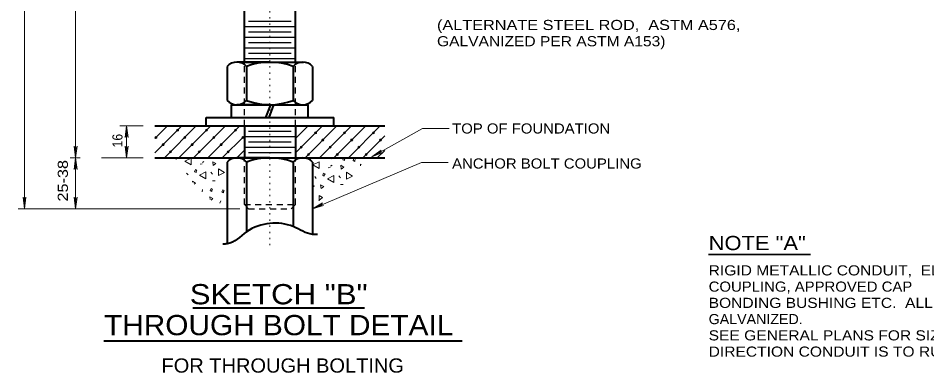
# Model space of a CAD drawing. Extents: x 312583 to 312854, y 144419 to 144597.
# Drawn here: x 312716.3 to 312784.5, y 144522.8 to 144549.4 of the extents above; entities that cross this region are included whole.
import ezdxf
from ezdxf.enums import TextEntityAlignment as Align

# ---------------------------------------------------------------- set-up
doc = ezdxf.new("R2010")
doc.units = 0
doc.header["$LTSCALE"] = 0.3
doc.header["$PDMODE"] = 32
doc.header["$PDSIZE"] = 0.15
doc.linetypes.add('DOTTED', pattern=[1.5, 0.3, -1.2])
doc.linetypes.add('SHORT_DASHED', pattern=[2.7, 1.5, -1.2])
doc.layers.add('1', color=7, linetype='Continuous', lineweight=25)
doc.layers.add('2', color=7, linetype='Continuous', lineweight=13)

msp = doc.modelspace()

# ---------------------------------------------------------------- linework, layer by layer
at = {"layer": '1', "linetype": 'DOTTED', "lineweight": 13}
msp.add_line((312735.2298, 144532.3427), (312735.2298, 144581.2407), dxfattribs=at)
at = {"layer": '1', "lineweight": 40}
for p, q in [((312733.3132, 144546.0967), (312733.3132, 144562.3884)), ((312737.1465, 144546.0967), (312737.1465, 144562.3884)), ((312735.2298, 144546.0967), (312732.7535, 144546.0967)), ((312733.3132, 144546.0967), (312737.7522, 144546.0967)), ((312735.2298, 144546.0967), (312737.6985, 144546.0967)), ((312732.0328, 144545.7747), (312732.0328, 144543.2217)), ((312733.4742, 144545.7747), (312733.4742, 144543.2217)), ((312733.4742, 144545.7747), (312733.4742, 144543.2217)), ((312736.9855, 144545.7747), (312736.9855, 144543.2217)), ((312738.4192, 144545.7747), (312738.4192, 144543.2217)), ((312732.3548, 144542.8997), (312738.0972, 144542.8997)), ((312732.3548, 144541.9414), (312732.3548, 144542.8997)), ((312735.2298, 144542.8997), (312732.7535, 144542.8997)), ((312734.9385, 144541.9414), (312735.2912, 144542.8997)), ((312735.1762, 144541.9414), (312735.5288, 144542.8997)), ((312735.2298, 144542.8997), (312737.6985, 144542.8997)), ((312738.0972, 144541.9414), (312738.0972, 144542.8997)), ((312730.4382, 144541.9414), (312740.0215, 144541.9414)), ((312730.4382, 144541.305), (312730.4382, 144541.9414)), ((312740.0215, 144541.305), (312740.0215, 144541.9414)), ((312726.6048, 144541.305), (312743.8472, 144541.305)), ((312733.3132, 144541.305), (312733.3132, 144538.913)), ((312737.1465, 144541.305), (312737.1465, 144538.913)), ((312726.6048, 144538.913), (312743.8472, 144538.913)), ((312732.0328, 144538.591), (312732.0328, 144532.45)), ((312735.2298, 144538.913), (312732.7535, 144538.913)), ((312733.3132, 144538.913), (312737.7522, 144538.913)), ((312733.4742, 144538.591), (312733.4742, 144533.347)), ((312733.4742, 144538.591), (312733.4742, 144536.038)), ((312735.2298, 144538.913), (312737.6985, 144538.913)), ((312736.9855, 144538.591), (312736.9855, 144533.7457)), ((312738.4192, 144538.591), (312738.4192, 144533.163))]:
    msp.add_line(p, q, dxfattribs=at)
at = {"layer": '1'}
for p, q in [((312733.3132, 144548.7724), (312737.1465, 144548.7724)), ((312733.6275, 144549.171), (312736.8245, 144549.171)), ((312733.6275, 144548.366), (312736.8245, 144548.366)), ((312733.3132, 144547.9674), (312737.1465, 144547.9674)), ((312733.6275, 144547.5687), (312736.8245, 144547.5687)), ((312733.3132, 144547.17), (312737.1465, 144547.17)), ((312733.6275, 144546.7637), (312736.8245, 144546.7637)), ((312733.3132, 144546.365), (312737.1465, 144546.365)), ((312733.6275, 144540.9064), (312736.8245, 144540.9064)), ((312733.3132, 144540.5077), (312737.1465, 144540.5077)), ((312733.6275, 144540.109), (312736.8245, 144540.109)), ((312733.3132, 144539.7104), (312737.1465, 144539.7104)), ((312733.6275, 144539.3117), (312736.8245, 144539.3117))]:
    msp.add_line(p, q, dxfattribs=at)
at = {"layer": '1', "linetype": 'SHORT_DASHED'}
for p, q in [((312733.3132, 144541.305), (312733.3132, 144546.0967)), ((312737.1465, 144541.305), (312737.1465, 144546.0967)), ((312733.3132, 144535.394), (312733.3132, 144538.913)), ((312737.1465, 144535.394), (312737.1465, 144538.913)), ((312733.3132, 144535.394), (312733.6275, 144535.0797)), ((312733.3132, 144535.394), (312737.1465, 144535.394)), ((312733.6275, 144535.0797), (312736.8245, 144535.0797)), ((312736.8245, 144535.0797), (312737.1465, 144535.394))]:
    msp.add_line(p, q, dxfattribs=at)
at = {"layer": '1', "lineweight": 40}
for centre, radius, start, end in [((312732.7505, 144545.1262), 0.9679, 42.07502, 137.92498), ((312735.2252, 144541.1048), 4.9893, 69.39031, 110.60969), ((312737.6999, 144545.1262), 0.9679, 42.07502, 137.92498), ((312732.7505, 144543.8689), 0.9679, 222.07502, 317.92498), ((312735.2252, 144547.8903), 4.9893, 249.39031, 290.60969), ((312737.6999, 144543.8689), 0.9679, 222.07502, 317.92498), ((312732.7505, 144537.9425), 0.9679, 42.07502, 137.92498), ((312735.2252, 144533.9211), 4.9893, 69.39031, 110.60969), ((312737.6999, 144537.9425), 0.9679, 42.07502, 137.92498)]:
    msp.add_arc(centre, radius, start, end, dxfattribs=at)
msp.add_spline([(312738.8025, 144533.163), (312738.4192, 144533.163), (312736.9855, 144533.7457), (312735.2298, 144533.9834), (312733.4742, 144533.347), (312732.0328, 144532.45), (312731.6955, 144532.427)], degree=3, dxfattribs=at)
at = {"layer": '2'}
for p, q in [((312716.8145, 144535.0797), (312716.8145, 144579.1554)), ((312725.7308, 144541.305), (312723.9752, 144541.305)), ((312724.4812, 144541.305), (312724.3738, 144540.4387)), ((312724.4812, 144538.913), (312724.4812, 144541.305)), ((312724.4812, 144541.305), (312724.5885, 144540.4387)), ((312726.6048, 144539.281), (312728.6288, 144541.305)), ((312726.6048, 144540.362), (312727.5478, 144541.305)), ((312727.3178, 144538.913), (312729.7098, 144541.305)), ((312728.4065, 144538.913), (312730.7985, 144541.305)), ((312729.4875, 144538.913), (312731.8872, 144541.305)), ((312730.5762, 144538.913), (312732.9682, 144541.305)), ((312737.1465, 144539.2734), (312739.1858, 144541.305)), ((312737.1465, 144540.3544), (312738.0972, 144541.305)), ((312737.8748, 144538.913), (312740.2668, 144541.305)), ((312738.9558, 144538.913), (312741.3478, 144541.305)), ((312740.0368, 144538.913), (312742.4365, 144541.305)), ((312741.1255, 144538.913), (312743.5175, 144541.305)), ((312724.3738, 144540.4387), (312724.4812, 144540.7147)), ((312724.5885, 144540.4387), (312724.4812, 144540.7147)), ((312731.6572, 144538.913), (312733.3132, 144540.569)), ((312742.2065, 144538.9054), (312743.8472, 144540.5537)), ((312742.8812, 144538.9744), (312746.6915, 144541.1057)), ((312746.6915, 144541.1057), (312748.6925, 144541.1057)), ((312720.5405, 144539.7794), (312720.6478, 144539.5034)), ((312720.6478, 144538.913), (312720.5405, 144539.7794)), ((312720.7552, 144539.7794), (312720.6478, 144539.5034)), ((312720.6478, 144538.913), (312720.7552, 144539.7794)), ((312724.3738, 144539.7794), (312724.4812, 144539.5034)), ((312724.4812, 144538.913), (312724.3738, 144539.7794)), ((312724.5885, 144539.7794), (312724.4812, 144539.5034)), ((312724.4812, 144538.913), (312724.5885, 144539.7794)), ((312732.7382, 144538.913), (312733.3132, 144539.4804)), ((312742.8812, 144538.9744), (312743.5865, 144539.4957)), ((312742.8812, 144538.9744), (312743.6938, 144539.304)), ((312743.2875, 144538.9054), (312743.8472, 144539.465)), ((312743.5865, 144539.4957), (312743.3948, 144539.2657)), ((312743.6938, 144539.304), (312743.3948, 144539.2657)), ((312720.9852, 144538.913), (312720.2415, 144538.913)), ((312720.6478, 144538.913), (312720.5405, 144538.0467)), ((312720.6478, 144538.913), (312720.7552, 144538.0467)), ((312725.7308, 144538.913), (312722.5875, 144538.913)), ((312728.2532, 144538.9054), (312728.1995, 144538.7904)), ((312730.1622, 144538.568), (312730.2848, 144538.637)), ((312738.4192, 144535.0874), (312746.5995, 144538.568)), ((312739.7455, 144538.9054), (312739.8758, 144538.8364)), ((312739.8758, 144538.8364), (312739.8758, 144538.913)), ((312740.8418, 144538.8057), (312740.8878, 144538.8824)), ((312746.5995, 144538.568), (312748.6082, 144538.568)), ((312720.5405, 144538.0467), (312720.6478, 144538.3227)), ((312720.7552, 144538.0467), (312720.6478, 144538.3227)), ((312729.9935, 144538.43), (312730.1392, 144538.4607)), ((312730.7985, 144537.832), (312730.9212, 144537.6787)), ((312739.5998, 144538.1617), (312739.7455, 144538.1847)), ((312739.7685, 144538.292), (312739.8988, 144538.361)), ((312728.9815, 144537.7707), (312729.0888, 144537.6327)), ((312730.9135, 144537.1804), (312731.1282, 144537.188)), ((312738.5955, 144537.5024), (312738.7028, 144537.3644)), ((312740.4048, 144537.556), (312740.5275, 144537.4027)), ((312730.1545, 144536.3524), (312730.1775, 144536.5364)), ((312740.5275, 144536.9044), (312740.7192, 144536.912)), ((312716.7072, 144535.946), (312716.8145, 144535.67)), ((312716.8145, 144535.0797), (312716.7072, 144535.946)), ((312716.9218, 144535.946), (312716.8145, 144535.67)), ((312716.8145, 144535.0797), (312716.9218, 144535.946)), ((312720.5405, 144535.946), (312720.6478, 144535.67)), ((312720.6478, 144535.0797), (312720.5405, 144535.946)), ((312720.7552, 144535.946), (312720.6478, 144535.67)), ((312720.6478, 144535.0797), (312720.7552, 144535.946)), ((312738.9022, 144535.7007), (312739.1858, 144535.923)), ((312738.9175, 144536.0764), (312738.9175, 144535.6777)), ((312739.1705, 144535.9307), (312738.9175, 144536.0764)), ((312732.9682, 144535.0797), (312716.3392, 144535.0797)), ((312731.5498, 144535.693), (312731.4732, 144535.5167)), ((312738.4192, 144535.0874), (312739.1782, 144535.5244)), ((312738.4192, 144535.0874), (312739.2625, 144535.3327)), ((312739.1782, 144535.5244), (312738.9635, 144535.3174)), ((312739.2625, 144535.3327), (312738.9635, 144535.3174))]:
    msp.add_line(p, q, dxfattribs=at)
at = {"layer": '2', "lineweight": 35}
msp.add_line((312768.1559, 144531.6469), (312775.7928, 144531.6469), dxfattribs=at)
at = {"layer": '2', "lineweight": 40}
for p, q in [((312729.4568, 144527.6335), (312742.3292, 144527.6335)), ((312722.7663, 144525.159), (312749.6704, 144525.159))]:
    msp.add_line(p, q, dxfattribs=at)
at = {"layer": '2'}
for points in [[(312720.6478, 144535.0797), (312720.6478, 144538.913), (312720.6478, 144569.572)], [(312740.7728, 144538.9207), (312740.7652, 144538.9054), (312740.7115, 144538.7674), (312740.8418, 144538.6984), (312740.8418, 144538.8057)], [(312740.8878, 144538.8824), (312740.7958, 144538.9054), (312740.7728, 144538.9207)], [(312742.0838, 144538.384), (312742.0225, 144538.43), (312742.0378, 144538.3074)], [(312729.5565, 144536.9427), (312729.6562, 144537.0194), (312729.4262, 144537.165), (312729.4338, 144537.0807)], [(312738.4268, 144536.6897), (312738.5572, 144536.7894), (312738.4268, 144536.8737)], [(312730.8138, 144535.739), (312730.9595, 144535.8464), (312730.7295, 144535.992), (312730.7602, 144535.7774)]]:
    msp.add_lwpolyline(points, dxfattribs=at)
for points in [[(312729.3188, 144538.3764), (312729.3188, 144538.89), (312728.8512, 144538.6524)], [(312730.9748, 144538.338), (312731.1665, 144538.4837), (312730.9365, 144538.6217)], [(312738.9252, 144538.1004), (312738.9252, 144538.614), (312738.4652, 144538.384)], [(312741.6085, 144538.7444), (312741.6545, 144538.8287), (312741.5395, 144538.867), (312741.4782, 144538.7137), (312741.6085, 144538.6447)], [(312729.7098, 144537.901), (312729.7558, 144537.9854), (312729.6408, 144538.0237), (312729.5795, 144537.8704), (312729.7098, 144537.8014)], [(312730.4152, 144537.3414), (312730.4152, 144537.855), (312729.9475, 144537.6174)], [(312731.3658, 144538.0927), (312731.3658, 144537.579), (312731.8335, 144537.809)], [(312740.5812, 144538.062), (312740.7805, 144538.2077), (312740.5428, 144538.3534)], [(312740.9722, 144537.8244), (312740.9722, 144537.303), (312741.4398, 144537.5407)], [(312739.3238, 144537.6327), (312739.3698, 144537.717), (312739.2548, 144537.7477), (312739.1935, 144537.602), (312739.3162, 144537.5254)], [(312740.0215, 144537.0654), (312740.0215, 144537.579), (312739.5538, 144537.3414)], [(312730.8828, 144536.4827), (312730.9288, 144536.567), (312730.8138, 144536.5977), (312730.7525, 144536.452), (312730.8828, 144536.3754)], [(312731.7568, 144536.383), (312731.8028, 144536.4674), (312731.6878, 144536.5057), (312731.6265, 144536.3524), (312731.7568, 144536.2757)], [(312739.0785, 144536.6054), (312739.2702, 144536.751), (312739.0325, 144536.889)]]:
    msp.add_lwpolyline(points, close=True, dxfattribs=at)
for p in [(312726.6815, 144540.4464), (312728.3068, 144540.983), (312728.8512, 144540.4464), (312730.4765, 144540.983), (312731.0208, 144540.4464), (312732.6462, 144540.983), (312733.1905, 144540.4464), (312738.6645, 144540.7837), (312740.8342, 144540.7837), (312743.0038, 144540.7837), (312727.2258, 144539.902), (312729.3955, 144539.902), (312731.5652, 144539.902), (312739.2088, 144540.247), (312741.3708, 144540.247), (312743.5405, 144540.247), (312727.7702, 144539.3577), (312729.9322, 144539.3577), (312732.1018, 144539.3577), (312737.5758, 144539.7027), (312738.1202, 144539.1584), (312739.7455, 144539.7027), (312740.2898, 144539.1584), (312741.9152, 144539.7027), (312742.4595, 144539.1584)]:
    msp.add_point(p, dxfattribs=at)

# ---------------------------------------------------------------- texts
for s, width, p in [('(ALTERNATE STEEL ROD,  ASTM A576,', 1.2, (312747.7721, 144548.5087)), ('GALVANIZED PER ASTM A153)', 1.15, (312747.7721, 144547.2887)), ('TOP OF FOUNDATION', 1.1, (312748.9082, 144540.7359)), ('ANCHOR BOLT COUPLING', 1.1, (312748.9061, 144538.1053)), ('RIGID METALLIC CONDUIT,  ELBOW,', 1.15, (312768.1605, 144530.0788)), ('COUPLING, APPROVED CAP', 1.1, (312768.1605, 144528.8588)), ('BONDING BUSHING ETC.  ALL MATERIAL', 1.15, (312768.1605, 144527.6388)), ('GALVANIZED.', 1.05, (312768.1605, 144526.4188)), ('SEE GENERAL PLANS FOR SIZE AND', 1.15, (312768.1605, 144525.1988)), ('DIRECTION CONDUIT IS TO RUN.', 1.15, (312768.1605, 144523.9788))]:
    msp.add_text(s, height=0.76, dxfattribs=dict(at, width=width)).set_placement(p)
for s, width, p in [('16', 0.9, (312724.168, 144539.6943)), ('25-38', 1.2, (312720.0709, 144535.6283))]:
    msp.add_text(s, height=0.76, rotation=90, dxfattribs=dict(at, width=width)).set_placement(p)
for s, height, width, p in [('NOTE "A"', 1.07, 1.15, (312771.8057, 144531.9786)), ('SKETCH "B"', 1.52, 1.15, (312735.8904, 144527.909)), ('THROUGH BOLT DETAIL', 1.52, 1.1, (312735.8904, 144525.589)), ('FOR THROUGH BOLTING', 1.07, 1.05, (312736.1938, 144522.7786))]:
    msp.add_text(s, height=height, dxfattribs=dict(at, width=width)).set_placement(p, align=Align.CENTER)

doc.saveas('drawing.dxf')
